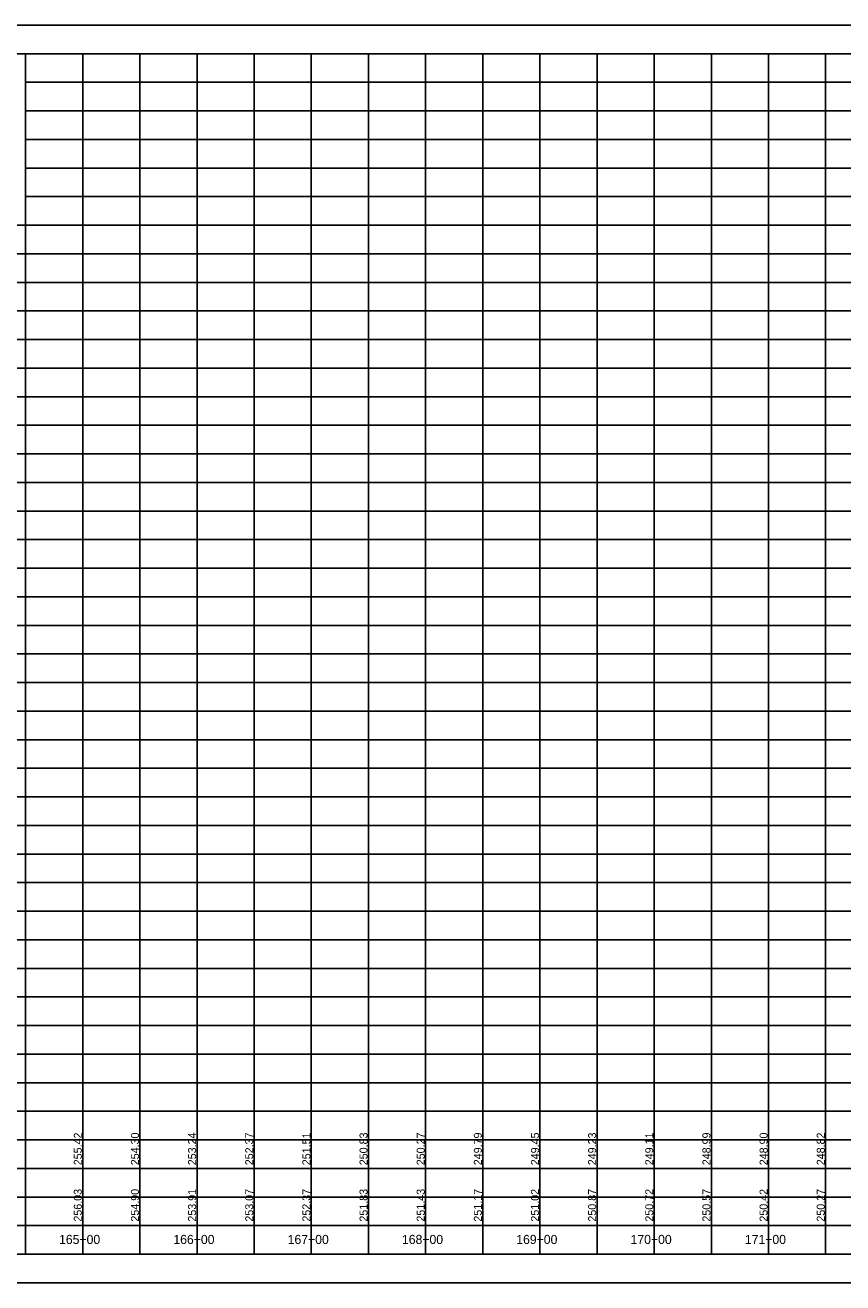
# Model space of a CAD drawing. Extents: x 1873632 to 1926512, y 813126 to 836257.
# Drawn here: x 1894813 to 1895528, y 828463 to 829563 of the extents above; entities that cross this region are included whole.
import ezdxf

# ---------------------------------------------------------------- set-up
doc = ezdxf.new("R2010")
doc.units = 0
for name, color, linetype in [('RD_DDB_StaTX', 7, 'Continuous'), ('RD_DDB_StripGrade', 7, 'Continuous'), ('RD_PD_WallFill', 7, 'Continuous'), ('RD_SHT_IplotShp', 7, 'Continuous')]:
    doc.layers.add(name, color=color, linetype=linetype)

msp = doc.modelspace()

# ---------------------------------------------------------------- linework, layer by layer
at = {"layer": 'RD_PD_WallFill'}
for p, q in [((1894362.9, 829538.1), (1899712.9, 829538.1)), ((1894362.9, 829538.1), (1896112.9, 829538.1)), ((1894812.9, 828488.1), (1894812.9, 829538.1)), ((1894812.9, 828488.1), (1894812.9, 829538.1)), ((1894862.9, 828488.1), (1894862.9, 829538.1)), ((1894862.9, 828488.1), (1894862.9, 829538.1)), ((1894912.9, 828488.1), (1894912.9, 829538.1)), ((1894912.9, 828488.1), (1894912.9, 829538.1)), ((1894962.9, 828488.1), (1894962.9, 829538.1)), ((1894962.9, 828488.1), (1894962.9, 829538.1)), ((1895012.9, 828488.1), (1895012.9, 829538.1)), ((1895012.9, 828488.1), (1895012.9, 829538.1)), ((1895062.9, 828488.1), (1895062.9, 829538.1)), ((1895062.9, 828488.1), (1895062.9, 829538.1)), ((1895112.9, 828488.1), (1895112.9, 829538.1)), ((1895112.9, 828488.1), (1895112.9, 829538.1)), ((1895162.9, 828488.1), (1895162.9, 829538.1)), ((1895162.9, 828488.1), (1895162.9, 829538.1)), ((1895212.9, 828488.1), (1895212.9, 829538.1)), ((1895212.9, 828488.1), (1895212.9, 829538.1)), ((1895262.9, 828488.1), (1895262.9, 829538.1)), ((1895262.9, 828488.1), (1895262.9, 829538.1)), ((1895312.9, 828488.1), (1895312.9, 829538.1)), ((1895312.9, 828488.1), (1895312.9, 829538.1)), ((1895362.9, 828488.1), (1895362.9, 829538.1)), ((1895362.9, 828488.1), (1895362.9, 829538.1)), ((1895412.9, 828488.1), (1895412.9, 829538.1)), ((1895412.9, 828488.1), (1895412.9, 829538.1)), ((1895462.9, 828488.1), (1895462.9, 829538.1)), ((1895462.9, 828488.1), (1895462.9, 829538.1)), ((1895512.9, 828488.1), (1895512.9, 829538.1)), ((1895512.9, 828488.1), (1895512.9, 829538.1)), ((1894812.9, 829513.1), (1899712.9, 829513.1)), ((1894812.9, 829513.1), (1899712.9, 829513.1)), ((1894812.9, 829488.1), (1899712.9, 829488.1)), ((1894812.9, 829463.1), (1899712.9, 829463.1)), ((1894812.9, 829438.1), (1899712.9, 829438.1)), ((1894812.9, 829413.1), (1899712.9, 829413.1)), ((1894362.9, 829388.1), (1899712.9, 829388.1)), ((1894362.9, 829363.1), (1899712.9, 829363.1)), ((1894362.9, 829338.1), (1899712.9, 829338.1)), ((1894362.9, 829313.1), (1899712.9, 829313.1)), ((1894362.9, 829288.1), (1899712.9, 829288.1)), ((1894362.9, 829263.1), (1899712.9, 829263.1)), ((1894362.9, 829238.1), (1899712.9, 829238.1)), ((1894362.9, 829213.1), (1899712.9, 829213.1)), ((1894362.9, 829188.1), (1899712.9, 829188.1)), ((1894362.9, 829163.1), (1899712.9, 829163.1)), ((1894362.9, 829138.1), (1899712.9, 829138.1)), ((1894362.9, 829113.1), (1899712.9, 829113.1)), ((1894362.9, 829088.1), (1899712.9, 829088.1)), ((1894362.9, 829063.1), (1899712.9, 829063.1)), ((1894362.9, 829038.1), (1899712.9, 829038.1)), ((1894362.9, 829013.1), (1899712.9, 829013.1)), ((1894362.9, 828988.1), (1899712.9, 828988.1)), ((1894362.9, 828963.1), (1899712.9, 828963.1)), ((1894362.9, 828938.1), (1899712.9, 828938.1)), ((1894362.9, 828913.1), (1899712.9, 828913.1)), ((1894362.9, 828888.1), (1899712.9, 828888.1)), ((1894362.9, 828863.1), (1899712.9, 828863.1)), ((1894362.9, 828838.1), (1899712.9, 828838.1)), ((1894362.9, 828813.1), (1899712.9, 828813.1)), ((1894362.9, 828788.1), (1899712.9, 828788.1)), ((1894362.9, 828763.1), (1899712.9, 828763.1)), ((1894362.9, 828738.1), (1899712.9, 828738.1)), ((1894362.9, 828713.1), (1899712.9, 828713.1)), ((1894362.9, 828688.1), (1899712.9, 828688.1)), ((1894362.9, 828663.1), (1899712.9, 828663.1)), ((1894362.9, 828638.1), (1899712.9, 828638.1)), ((1894362.9, 828613.1), (1899712.9, 828613.1)), ((1894362.9, 828588.1), (1899712.9, 828588.1)), ((1894362.9, 828563.1), (1899712.9, 828563.1)), ((1894362.9, 828538.1), (1899712.9, 828538.1)), ((1894362.9, 828513.1), (1899712.9, 828513.1)), ((1894362.9, 828488.1), (1899712.9, 828488.1)), ((1894362.9, 828488.1), (1899712.9, 828488.1))]:
    msp.add_line(p, q, dxfattribs=at)
msp.add_lwpolyline([(1894412.9, 829538.1), (1894812.9, 829538.1), (1894812.9, 829388.1), (1894412.9, 829388.1)], close=True, dxfattribs=at)
msp.add_lwpolyline([(1894412.9, 829538.1), (1894812.9, 829538.1), (1894812.9, 829388.1), (1894412.9, 829388.1)], close=True, dxfattribs=at)
msp.add_lwpolyline([(1894412.9, 829538.1), (1894812.9, 829538.1), (1894812.9, 829388.1), (1894412.9, 829388.1)], close=True, dxfattribs=at)
msp.add_lwpolyline([(1894412.9, 829538.1), (1894812.9, 829538.1), (1894812.9, 829388.1), (1894412.9, 829388.1)], close=True, dxfattribs=at)
at = {"layer": 'RD_SHT_IplotShp'}
msp.add_lwpolyline([(1894337.8, 828463.1), (1899737.8, 828463.1), (1899737.8, 829563.1), (1894337.8, 829563.1)], close=True, dxfattribs=at)

# ---------------------------------------------------------------- texts
at = {"layer": 'RD_DDB_StaTX'}
for s, p in [('165+00', (1894842.2, 828497)), ('166+00', (1894942.2, 828497)), ('167+00', (1895042.2, 828497)), ('168+00', (1895142.2, 828497)), ('169+00', (1895242.2, 828497)), ('170+00', (1895342.2, 828497)), ('171+00', (1895442.2, 828497))]:
    msp.add_text(s, height=8, dxfattribs=at).set_placement(p)
at = {"layer": 'RD_DDB_StripGrade'}
for s, p in [('255.42', (1894862.1, 828565.9)), ('254.30', (1894912.1, 828565.9)), ('253.24', (1894962.1, 828565.9)), ('252.37', (1895012.1, 828565.9)), ('251.51', (1895062.1, 828565.9)), ('250.83', (1895112.1, 828565.9)), ('250.27', (1895162.1, 828565.9)), ('249.79', (1895212.1, 828565.9)), ('249.45', (1895262.1, 828565.9)), ('249.23', (1895312.1, 828565.9)), ('249.11', (1895362.1, 828565.9)), ('248.99', (1895412.1, 828565.9)), ('248.90', (1895462.1, 828565.9)), ('248.82', (1895512.1, 828565.9)), ('256.03', (1894862.1, 828516.6)), ('254.90', (1894912.1, 828516.6)), ('253.91', (1894962.1, 828516.6)), ('253.07', (1895012.1, 828516.6)), ('252.37', (1895062.1, 828516.6)), ('251.83', (1895112.1, 828516.6)), ('251.43', (1895162.1, 828516.6)), ('251.17', (1895212.1, 828516.6)), ('251.02', (1895262.1, 828516.6)), ('250.87', (1895312.1, 828516.6)), ('250.72', (1895362.1, 828516.6)), ('250.57', (1895412.1, 828516.6)), ('250.42', (1895462.1, 828516.6)), ('250.27', (1895512.1, 828516.6))]:
    msp.add_text(s, height=7, rotation=90, dxfattribs=at).set_placement(p)

doc.saveas('drawing.dxf')
